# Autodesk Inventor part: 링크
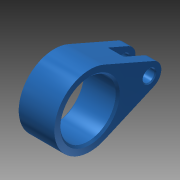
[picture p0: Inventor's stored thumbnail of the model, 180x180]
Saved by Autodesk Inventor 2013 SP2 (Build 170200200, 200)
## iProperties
Created: 2016-08
Part Number: 링크
Material: 강철, 탄소
Document SubType Name: Modeling
Designer: mduedu
Density: 7.87 g/cm^3
Author: mduedu
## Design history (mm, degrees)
sketch "스케치1"
  geometry: L1 (32.4, 5.499)-(7.2, 16.497); L2 (32.4, -5.499)-(7.2, -16.497); C1 r 14 at (0, 0); C2 r 3 at (30, 0); A1 r 18 centre (0, 0) between (7.2, 16.497) and (7.2, -16.497); A2 r 6 centre (30, 0) between (32.4, 5.499) and (32.4, -5.499); 1 further point
  constraints: 4 centre point, 4 end point, 4 point on circle, 4 tangent, 3 coincident, 1 horizontal alignment
  dimensions: "d0" = 36 diameter of A1; "d2" = 12 diameter of A2; "d3" = 30 distance of A2.centre point (0, 0); "d4" = 28 diameter of C1; "d5" = 6 diameter of C2
extrude "돌출1" new body sketch "스케치1" stored distance "d6" = 18; taper "d7" = 0 deg
sketch "스케치2"
  geometry: L1 (-9, 36)-(9, 36) reference; L2 (0, 0)-(0, 36); L3 (-4, 36)-(4, 36); L4 (4, 36)-(4, 22); L5 (4, 22)-(-4, 22); L6 (-4, 22)-(-4, 36)
  constraints: 10 end point, 2 midpoint, 2 parallel, 1 horizontal, 1 perpendicular, 1 point on line
  dimensions: "d8" = 8 distance between parallel lines of L4 L6; "d10" = 14 distance of L3.end L4.end
extrude "돌출2" cut sketch "스케치2" stored distance "d11" = 20; taper "d12" = 0 deg
chamfer "모따기1" distance "d13" = 1; stored, may be unused: second distance "d14" = 2, angle "d15" = 45 deg
chamfer "모따기2" distance "d16" = 0.5; stored, may be unused: second distance "d17" = 2, angle "d18" = 45 deg
node "솔리드1"
